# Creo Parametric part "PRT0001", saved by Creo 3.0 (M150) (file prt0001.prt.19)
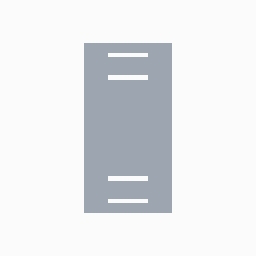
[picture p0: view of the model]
Units: millimeter Newton Second (mmNs); MM, TONNE, SECS

Created from: INLBS_PART_SOLID.PRT

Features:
  1. datum plane "RIGHT"
  2. datum plane "TOP"
  3. datum plane "FRONT"
  4. coordinate system
  5. sketch "Sketch 1"
  6. sketch "Sketch 2"
  7. extrusion "Extrude 1"
  8. extruded cut "Extrude 2"

Surfaces: 25 plane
